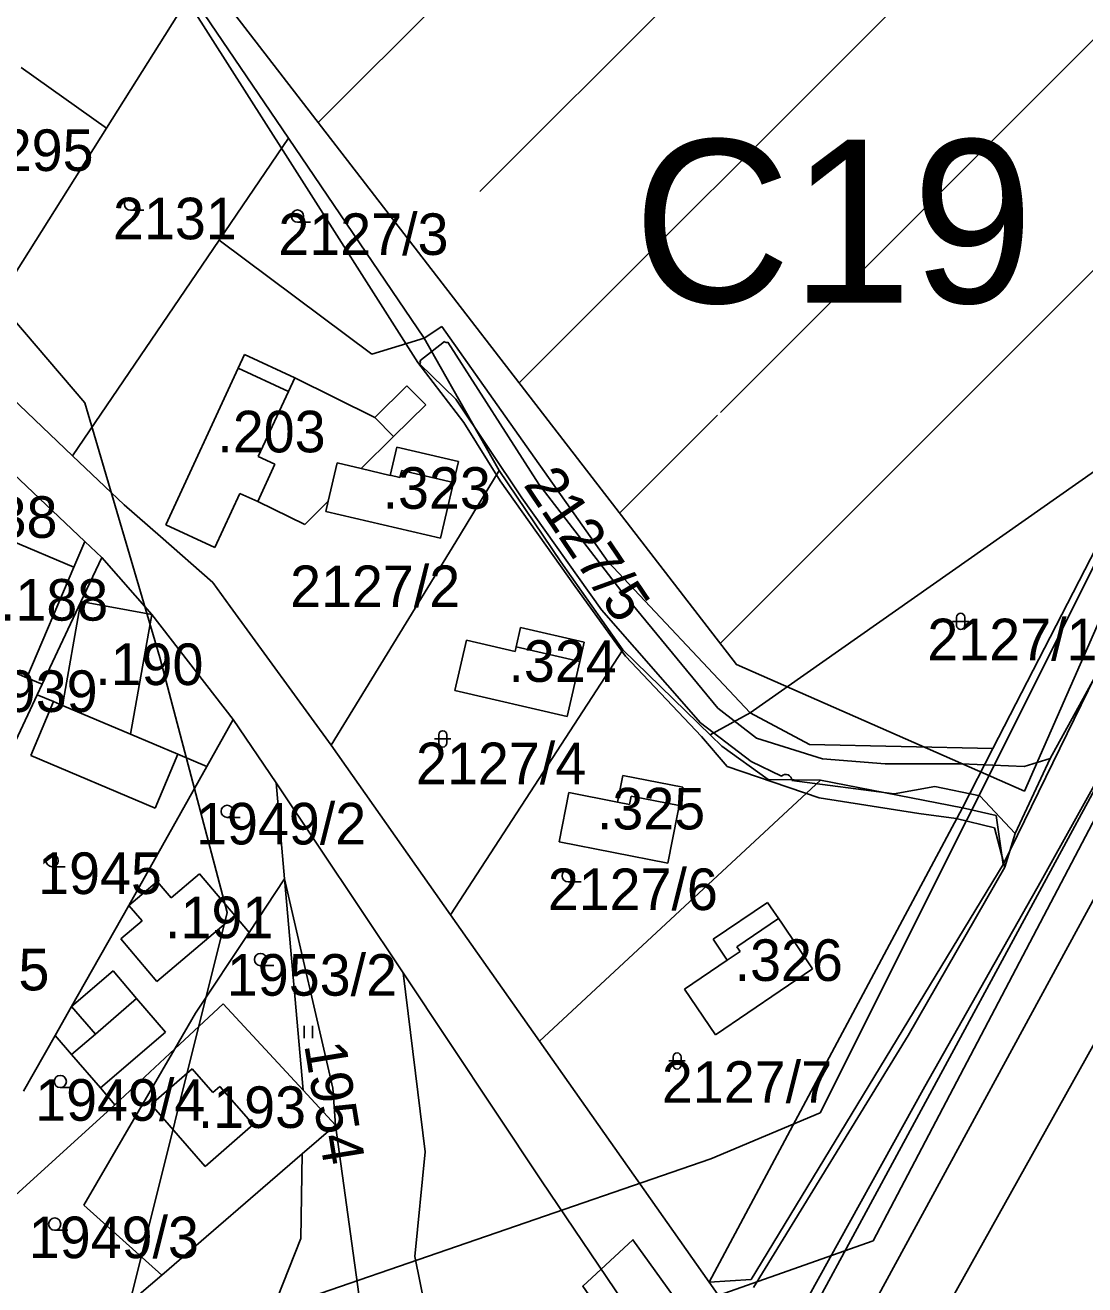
# Model space of a CAD drawing. Extents: x -564810 to -550519, y -1045831 to -1034011.
# Drawn here: x -553050.1 to -552920.1, y -1037817.5 to -1037663 of the extents above; entities that cross this region are included whole.
import ezdxf

# ---------------------------------------------------------------- set-up
doc = ezdxf.new("R2010")
doc.units = 0
for name, color, linetype in [('KN stav', 7, 'Continuous'), ('Lesní porost', 7, 'Continuous'), ('Obvod KPU', 7, 'Continuous'), ('označ pol cest', 7, 'Continuous'), ('Parcelní čísla', 7, 'Continuous'), ('Polní cesty stavající', 7, 'Continuous'), ('STG', 7, 'Continuous'), ('Vedení VN', 7, 'Continuous'), ('Vrstva 22', 7, 'Continuous'), ('Vrstva 39', 7, 'Continuous'), ('Vrstva 4', 7, 'Continuous'), ('Vrstva 5', 7, 'Continuous'), ('zamokř ploch', 7, 'Continuous')]:
    doc.layers.add(name, color=color, linetype=linetype)

msp = doc.modelspace()

# ---------------------------------------------------------------- linework, layer by layer
at = {"layer": 'KN stav'}
for p, q in [((-553029.74, -1037659.19), (-553040.1, -1037675.65)), ((-553017.77, -1037676.87), (-553029.74, -1037659.19)), ((-553040.1, -1037675.65), (-553050.55, -1037668.18)), ((-553040.1, -1037675.65), (-553057.47, -1037703.22)), ((-553017.77, -1037676.87), (-553026.28, -1037689.38)), ((-553001.14, -1037701.4), (-553017.77, -1037676.87)), ((-553026.28, -1037689.38), (-553044.24, -1037715.8)), ((-553007.55, -1037703.35), (-553026.28, -1037689.38)), ((-552998.99, -1037699.95), (-553001.14, -1037701.4)), ((-552978.62, -1037728.76), (-552998.99, -1037699.95)), ((-553001.14, -1037701.4), (-553004.2, -1037702.31)), ((-553001.14, -1037701.4), (-552999.17, -1037704.88)), ((-553004.2, -1037702.31), (-553007.55, -1037703.35)), ((-553057.47, -1037703.22), (-553044.24, -1037715.8)), ((-553023.94, -1037705.08), (-553023.16, -1037703.4)), ((-553023.16, -1037703.4), (-553017, -1037706.25)), ((-553032.82, -1037724.27), (-553023.94, -1037705.08)), ((-552999.17, -1037704.88), (-552991.93, -1037717.63)), ((-553017, -1037706.25), (-553007.21, -1037711.13)), ((-553007.21, -1037711.13), (-553003.26, -1037707.22)), ((-553003.26, -1037707.22), (-553002.45, -1037708.03)), ((-553002.45, -1037708.03), (-553000.95, -1037709.55)), ((-553000.95, -1037709.55), (-553004.9, -1037713.46)), ((-552911.07, -1037712.13), (-552961.16, -1037747.33)), ((-552931.42, -1037751.72), (-552911.07, -1037712.13)), ((-553004.9, -1037713.46), (-553008.86, -1037717.38)), ((-553005.31, -1037718.21), (-553004.5, -1037714.74)), ((-553004.5, -1037714.74), (-552996.95, -1037716.5)), ((-553044.24, -1037715.8), (-553037.91, -1037721.82)), ((-553011.81, -1037716.69), (-553012.91, -1037721.39)), ((-553008.86, -1037717.38), (-553011.81, -1037716.69)), ((-552996.95, -1037716.5), (-552997.55, -1037719.09)), ((-553042.73, -1037726.32), (-553051.49, -1037718.01)), ((-553008.86, -1037717.38), (-553005.31, -1037718.21)), ((-552997.27, -1037726.36), (-552991.93, -1037717.63)), ((-552991.93, -1037717.63), (-552997.27, -1037726.36)), ((-552991.93, -1037717.63), (-552984.37, -1037728.82)), ((-552984.37, -1037728.82), (-552991.93, -1037717.63)), ((-552997.55, -1037719.09), (-552999.15, -1037725.92)), ((-553023.73, -1037720.42), (-553026.8, -1037727.06)), ((-553021.55, -1037721.43), (-553023.73, -1037720.42)), ((-553015.77, -1037724.22), (-553021.55, -1037721.43)), ((-553012.91, -1037721.39), (-553015.77, -1037724.22)), ((-553013.2, -1037722.64), (-553012.91, -1037721.39)), ((-553037.91, -1037721.82), (-553033.48, -1037725.7)), ((-552999.15, -1037725.92), (-553013.2, -1037722.64)), ((-553026.8, -1037727.06), (-553032.82, -1037724.27)), ((-553040.67, -1037728.27), (-553042.73, -1037726.32)), ((-553033.48, -1037725.7), (-553027.04, -1037731.35)), ((-553012.54, -1037751.32), (-552997.27, -1037726.36)), ((-552997.27, -1037726.36), (-553012.54, -1037751.32)), ((-553043.22, -1037733.71), (-553040.67, -1037728.27)), ((-553034.53, -1037735.26), (-553040.67, -1037728.27)), ((-552984.37, -1037728.82), (-552976.8, -1037739.63)), ((-552976.8, -1037739.63), (-552984.37, -1037728.82)), ((-552961.16, -1037747.33), (-552978.62, -1037728.76)), ((-553027.04, -1037731.35), (-553024.91, -1037734.28)), ((-553047.97, -1037743.84), (-553043.22, -1037733.71)), ((-553024.56, -1037748.16), (-553034.53, -1037735.26)), ((-553024.91, -1037734.28), (-553012.54, -1037751.32)), ((-552900.02, -1037735.13), (-552954.01, -1037834.49)), ((-552989.32, -1037736.89), (-552989.86, -1037739.25)), ((-552989.86, -1037739.25), (-552989.32, -1037736.89)), ((-552981.52, -1037738.69), (-552989.32, -1037736.89)), ((-552989.32, -1037736.89), (-552981.52, -1037738.69)), ((-552995.96, -1037738.42), (-552997.39, -1037744.58)), ((-552997.39, -1037744.58), (-552995.96, -1037738.42)), ((-552989.99, -1037739.8), (-552995.96, -1037738.42)), ((-552995.96, -1037738.42), (-552989.99, -1037739.8)), ((-553057.58, -1037739.76), (-553049.84, -1037743.05)), ((-552976.8, -1037739.63), (-552997.91, -1037772.1)), ((-552997.91, -1037772.1), (-552976.8, -1037739.63)), ((-552989.86, -1037739.25), (-552989.99, -1037739.8)), ((-552989.99, -1037739.8), (-552989.86, -1037739.25)), ((-552982.06, -1037741.06), (-552981.52, -1037738.69)), ((-552981.52, -1037738.69), (-552982.06, -1037741.06)), ((-552976.8, -1037739.63), (-552966, -1037750.11)), ((-552966, -1037750.11), (-552976.8, -1037739.63)), ((-552983.62, -1037747.77), (-552982.06, -1037741.06)), ((-552982.06, -1037741.06), (-552983.62, -1037747.77)), ((-553049.84, -1037743.05), (-553047.97, -1037743.84)), ((-553048.57, -1037745.12), (-553047.97, -1037743.84)), ((-552997.39, -1037744.58), (-552983.62, -1037747.77)), ((-552983.62, -1037747.77), (-552997.39, -1037744.58)), ((-553056.54, -1037762.09), (-553048.57, -1037745.12)), ((-553046.59, -1037745.96), (-553049.38, -1037752.56)), ((-553048.57, -1037745.12), (-553046.59, -1037745.96)), ((-552953.88, -1037751.23), (-552961.16, -1037747.33)), ((-553024.56, -1037748.16), (-553027.79, -1037753.92)), ((-553019.29, -1037755.93), (-553024.56, -1037748.16)), ((-552966, -1037750.11), (-552964.63, -1037751.44)), ((-552964.63, -1037751.44), (-552966, -1037750.11)), ((-553049.38, -1037752.56), (-553034.12, -1037759.02)), ((-553034.12, -1037759.02), (-553031.33, -1037752.42)), ((-553031.33, -1037752.42), (-553027.79, -1037753.92)), ((-553012.54, -1037751.32), (-552997.91, -1037772.1)), ((-552997.91, -1037772.1), (-553012.54, -1037751.32)), ((-552964.63, -1037751.44), (-552958.98, -1037755.51)), ((-552958.98, -1037755.51), (-552964.63, -1037751.44)), ((-552931.42, -1037751.72), (-552953.88, -1037751.23)), ((-552935.15, -1037758.98), (-552931.42, -1037751.72)), ((-553027.79, -1037753.92), (-553037.34, -1037770.96)), ((-552952.54, -1037755.59), (-552987.02, -1037787.59)), ((-552987.02, -1037787.59), (-552952.54, -1037755.59)), ((-552976.78, -1037755.01), (-552977.43, -1037758.3)), ((-552977.43, -1037758.3), (-552976.78, -1037755.01)), ((-552969.44, -1037756.46), (-552976.78, -1037755.01)), ((-552976.78, -1037755.01), (-552969.44, -1037756.46)), ((-552958.98, -1037755.51), (-552952.54, -1037755.59)), ((-552952.54, -1037755.59), (-552958.98, -1037755.51)), ((-552952.54, -1037755.59), (-552935.15, -1037758.98)), ((-552935.15, -1037758.98), (-552952.54, -1037755.59)), ((-553003.73, -1037779.23), (-553019.29, -1037755.93)), ((-553019.29, -1037755.93), (-553018.25, -1037767.71)), ((-552983.4, -1037757.12), (-552984.6, -1037763.15)), ((-552984.6, -1037763.15), (-552983.4, -1037757.12)), ((-552977.43, -1037758.3), (-552983.4, -1037757.12)), ((-552983.4, -1037757.12), (-552977.43, -1037758.3)), ((-552969.88, -1037758.72), (-552969.44, -1037756.46)), ((-552969.44, -1037756.46), (-552969.88, -1037758.72)), ((-552970.09, -1037759.76), (-552969.88, -1037758.72)), ((-552969.88, -1037758.72), (-552970.09, -1037759.76)), ((-552971.28, -1037765.78), (-552970.09, -1037759.76)), ((-552970.09, -1037759.76), (-552971.28, -1037765.78)), ((-552935.15, -1037758.98), (-552931, -1037759.93)), ((-552931, -1037759.93), (-552935.15, -1037758.98)), ((-552931, -1037759.93), (-552930.17, -1037765.92)), ((-552930.17, -1037765.92), (-552931, -1037759.93)), ((-552984.6, -1037763.15), (-552971.28, -1037765.78)), ((-552971.28, -1037765.78), (-552984.6, -1037763.15)), ((-552930.17, -1037765.92), (-552961.04, -1037816.83)), ((-552961.04, -1037816.83), (-552930.17, -1037765.92)), ((-553037.34, -1037770.96), (-553033.88, -1037768.02)), ((-553033.88, -1037768.02), (-553032.18, -1037770.03)), ((-553032.18, -1037770.03), (-553028.69, -1037767.08)), ((-553028.69, -1037767.08), (-553024.35, -1037772.2)), ((-553018.25, -1037767.71), (-553022.6, -1037774.27)), ((-553012.33, -1037793.36), (-553018.25, -1037767.71)), ((-553015.97, -1037793.61), (-553018.25, -1037767.71)), ((-553037.34, -1037770.96), (-553044.36, -1037783.36)), ((-552959.05, -1037770.59), (-552965.72, -1037775.11)), ((-552965.72, -1037775.11), (-552959.05, -1037770.59)), ((-552957.31, -1037773.15), (-552959.05, -1037770.59)), ((-552959.05, -1037770.59), (-552957.31, -1037773.15)), ((-553024.35, -1037772.2), (-553022.6, -1037774.27)), ((-552997.91, -1037772.1), (-552987.02, -1037787.59)), ((-552987.02, -1037787.59), (-552997.91, -1037772.1)), ((-552953.52, -1037778.74), (-552957.31, -1037773.15)), ((-552957.31, -1037773.15), (-552953.52, -1037778.74)), ((-553022.6, -1037774.27), (-553029.17, -1037784.19)), ((-552965.72, -1037775.11), (-552963.98, -1037777.68)), ((-552963.98, -1037777.68), (-552965.72, -1037775.11)), ((-552963.98, -1037777.68), (-552969.23, -1037781.24)), ((-552969.23, -1037781.24), (-552963.98, -1037777.68)), ((-552965.44, -1037786.83), (-552953.52, -1037778.74)), ((-552953.52, -1037778.74), (-552965.44, -1037786.83)), ((-552986.77, -1037804.73), (-553003.73, -1037779.23)), ((-553003.73, -1037779.23), (-553001.02, -1037801.18)), ((-552969.23, -1037781.24), (-552965.44, -1037786.83)), ((-552965.44, -1037786.83), (-552969.23, -1037781.24)), ((-553044.36, -1037783.36), (-553046.38, -1037786.91)), ((-553031.7, -1037788.54), (-553025.77, -1037783.01)), ((-553025.77, -1037783.01), (-553015.97, -1037793.61)), ((-553029.17, -1037784.19), (-553031.7, -1037788.54)), ((-553050.27, -1037793.76), (-553046.38, -1037786.91)), ((-553046.38, -1037786.91), (-553044.37, -1037789.25)), ((-552987.02, -1037787.59), (-552966.19, -1037817.18)), ((-552966.19, -1037817.18), (-552987.02, -1037787.59)), ((-553044.37, -1037789.25), (-553040.84, -1037793.35)), ((-553031.7, -1037788.54), (-553042.85, -1037807.74)), ((-553039.07, -1037795.41), (-553031.7, -1037788.54)), ((-553040.84, -1037793.35), (-553039.07, -1037795.41)), ((-553015.97, -1037793.61), (-553012.02, -1037797.89)), ((-553012.02, -1037797.89), (-553012.33, -1037793.36)), ((-553039.07, -1037795.41), (-553058.2, -1037812.81)), ((-553012.02, -1037797.89), (-553016.1, -1037801.42)), ((-553012.02, -1037797.89), (-553008.07, -1037826.39)), ((-553033.3, -1037816.3), (-553016.1, -1037801.42)), ((-553016.1, -1037801.42), (-553016.27, -1037811.79)), ((-553001.02, -1037801.18), (-553002.27, -1037814.03)), ((-552971.26, -1037827.61), (-552986.77, -1037804.73)), ((-553042.85, -1037807.74), (-553033.3, -1037816.3)), ((-553016.27, -1037811.79), (-553022.22, -1037826.9)), ((-553002.27, -1037814.03), (-553001.03, -1037820.27)), ((-553033.3, -1037816.3), (-553037.74, -1037820.11)), ((-552961.04, -1037816.83), (-552966.19, -1037817.18)), ((-552966.19, -1037817.18), (-552961.04, -1037816.83)), ((-552966.19, -1037817.18), (-552954.01, -1037834.49))]:
    msp.add_line(p, q, dxfattribs=at)
at = {"layer": 'Lesní porost'}
for p, q in [((-553014.14, -1037674.95), (-552911.77, -1037572.58)), ((-552994.3, -1037683.39), (-552911.47, -1037600.57)), ((-552989.5, -1037706.88), (-552911.17, -1037628.55)), ((-552964.83, -1037710.49), (-552910.96, -1037656.63)), ((-552964.87, -1037738.82), (-552911.01, -1037684.96)), ((-552977.18, -1037722.85), (-552965.18, -1037710.85))]:
    msp.add_line(p, q, dxfattribs=at)
at = {"layer": 'Obvod KPU'}
for p, q in [((-553029.69, -1037660.7), (-553018.13, -1037678.87)), ((-553018.13, -1037678.87), (-553001.91, -1037704.35)), ((-553001.91, -1037704.35), (-552996.27, -1037711.74)), ((-552996.27, -1037711.74), (-552991.81, -1037718.9)), ((-552991.81, -1037718.9), (-552982.64, -1037731.83)), ((-552982.64, -1037731.83), (-552976.44, -1037740.39)), ((-552976.44, -1037740.39), (-552967.16, -1037750.24)), ((-552967.16, -1037750.24), (-552963.99, -1037753.94)), ((-552963.99, -1037753.94), (-552952.7, -1037757.75)), ((-552952.7, -1037757.75), (-552940.48, -1037759.68)), ((-552940.48, -1037759.68), (-552935.91, -1037760.31)), ((-552935.91, -1037760.31), (-552931.21, -1037761.44)), ((-552931.21, -1037761.44), (-552929.97, -1037766.27)), ((-552929.97, -1037766.27), (-552941.8, -1037786.93)), ((-552941.8, -1037786.93), (-552960.76, -1037817.81))]:
    msp.add_line(p, q, dxfattribs=at)
at = {"layer": 'Polní cesty stavající'}
for p, q in [((-552998.65, -1037701.81), (-553001.67, -1037704.17)), ((-552987.08, -1037719.28), (-552998.25, -1037701.88)), ((-553001.69, -1037704.56), (-552997.26, -1037708.86)), ((-552997.26, -1037708.86), (-552989.18, -1037720.98)), ((-552977.03, -1037732.33), (-552987.08, -1037719.28)), ((-552989.18, -1037720.98), (-552979.39, -1037734.72)), ((-552965.15, -1037746.75), (-552977.03, -1037732.33)), ((-552979.39, -1037734.72), (-552967.28, -1037748.56)), ((-552960.39, -1037750.44), (-552965.15, -1037746.75)), ((-552967.28, -1037748.56), (-552961.05, -1037753.29)), ((-552952.3, -1037753), (-552960.39, -1037750.44)), ((-552961.05, -1037753.29), (-552957.33, -1037755.12)), ((-552944.62, -1037753.6), (-552952.3, -1037753)), ((-552935.27, -1037753.61), (-552944.62, -1037753.6)), ((-552927.57, -1037753.94), (-552935.27, -1037753.61)), ((-552924.38, -1037752.93), (-552927.57, -1037753.94)), ((-552956.05, -1037755.62), (-552943.53, -1037757.29)), ((-552943.53, -1037757.29), (-552938.52, -1037756.37)), ((-552938.52, -1037756.37), (-552933.01, -1037757.52)), ((-552933.01, -1037757.52), (-552928.67, -1037762.15))]:
    msp.add_line(p, q, dxfattribs=at)
for points in [[(-552960.76, -1037817.81), (-552941.8, -1037786.93), (-552929.97, -1037766.27), (-552928.67, -1037762.15), (-552924.38, -1037752.93), (-552903.4, -1037714.73), (-552892.53, -1037691.5), (-552885, -1037675.77), (-552874.67, -1037648.23), (-552874.67, -1037648.23), (-552861.2, -1037606.24), (-552850.78, -1037573.23), (-552844.27, -1037541.11), (-552842.11, -1037542.55), (-552841.6, -1037538.6), (-552840.92, -1037529.94), (-552837.72, -1037513.24), (-552840.45, -1037515.35), (-552825.68, -1037468.2), (-552803.94, -1037397.99), (-552790.46, -1037357.53)], [(-552785.17, -1037359.05), (-552797.5, -1037398.18), (-552820.92, -1037471.8), (-552833.6, -1037513.63), (-552835.28, -1037521.77), (-552837.42, -1037534.38), (-552834.86, -1037539.46), (-552825.88, -1037544.97), (-552818.86, -1037554.44), (-552823.67, -1037553.78), (-552826.56, -1037549.47), (-552831.77, -1037545.13), (-552834.93, -1037543.55), (-552838.51, -1037542.9), (-552845.29, -1037574.84), (-552855.41, -1037608.33), (-552866.99, -1037642.38), (-552869.53, -1037649.96), (-552879.97, -1037677.73), (-552887.48, -1037694.58), (-552912.55, -1037744.63), (-552925.5, -1037767.94), (-552939.75, -1037793.18), (-552954.11, -1037819.1)], [(-552928.67, -1037762.15), (-552924.38, -1037752.93)]]:
    msp.add_lwpolyline(points, dxfattribs=at)
for centre, radius, start, end in [((-552998.41, -1037701.63), 0.3, 217.8523, 302.6975), ((-553001.91, -1037704.35), 0.3, 315.8756, 37.8523), ((-552956.8, -1037755.65), 0.75, 2.5466, 134.5767)]:
    msp.add_arc(centre, radius, start, end, dxfattribs=at)
at = {"layer": 'STG'}
msp.add_lwpolyline([(-553069.37, -1037817.75), (-553060.19, -1037787.43), (-553060.19, -1037767.22), (-553071.21, -1037738.73), (-553073.97, -1037702.9), (-553068.46, -1037687.28), (-553059.27, -1037690.04), (-553042.74, -1037709.33), (-553033.55, -1037740.57), (-553025.28, -1037771.81), (-553038.14, -1037823.26)], dxfattribs=at)
at = {"layer": 'Vedení VN'}
msp.add_line((-552946.11, -1037812.08), (-553022.11, -1037838.91), dxfattribs=at)
for points in [[(-554311.13, -1038894.55), (-554183.26, -1038768.06), (-553948.71, -1038736.97), (-553887.24, -1038715.77), (-553721.22, -1038534.86), (-553615.96, -1038471.97), (-553583.46, -1038409.78), (-553495.15, -1038284), (-553204.09, -1037884.03), (-552966, -1037802.05), (-552952.58, -1037796.4), (-552903.13, -1037697.47), (-552835.31, -1037471.34), (-552755.48, -1037231.07), (-552629.72, -1036976.67), (-552323.11, -1036754.78)], [(-552318.17, -1036790.68), (-552611.35, -1036998.44), (-552747, -1037286.75), (-552886.17, -1037729.13), (-552939.86, -1037825.23), (-553193.49, -1037916.39), (-553506.46, -1038353.11), (-553565.8, -1038423.21), (-553601.83, -1038493.17), (-553700.74, -1038549.7), (-553878.06, -1038746.16), (-554195.97, -1038818.23), (-554311.84, -1038929.18)], [(-552758.55, -1037278.62), (-552793.93, -1037392.61), (-552821.07, -1037475.75), (-552845.16, -1037552.06), (-552871.05, -1037634.86), (-552897.88, -1037720.24), (-552946.11, -1037812.08)]]:
    msp.add_lwpolyline(points, dxfattribs=at)
at = {"layer": 'Vrstva 39'}
msp.add_lwpolyline([(-552897.12, -1037940.43), (-552898.9, -1037938.1), (-552945.1, -1037870.48), (-552981.69, -1037817.65), (-552975.54, -1037811.96), (-552969.36, -1037820.6), (-552960.29, -1037833.27), (-552959.84, -1037829.57)], dxfattribs=at)
at = {"layer": 'Vrstva 4'}
for p, q in [((-553023.94, -1037705.08), (-553017.78, -1037707.93)), ((-553017.78, -1037707.93), (-553017, -1037706.25)), ((-553017.78, -1037707.93), (-553021.48, -1037715.91)), ((-553004.9, -1037713.46), (-553007.21, -1037711.12)), ((-553019.43, -1037716.86), (-553021.55, -1037721.43)), ((-553021.48, -1037715.91), (-553019.43, -1037716.86)), ((-553004.11, -1037718.49), (-553005.31, -1037718.2)), ((-553003.9, -1037717.61), (-553004.11, -1037718.49)), ((-552997.55, -1037719.09), (-553003.9, -1037717.61)), ((-553044.08, -1037729.49), (-553051.8, -1037726.21)), ((-553044.08, -1037729.49), (-553042.73, -1037726.31)), ((-553049.84, -1037743.05), (-553044.08, -1037729.49)), ((-553045.49, -1037746.42), (-553043.22, -1037733.7)), ((-553034.53, -1037735.26), (-553043.22, -1037733.7)), ((-553037.16, -1037749.95), (-553034.53, -1037735.26)), ((-552982.07, -1037741.06), (-552989.86, -1037739.25)), ((-552917.97, -1037741.01), (-552930.17, -1037765.92)), ((-553045.49, -1037746.42), (-553046.59, -1037745.96)), ((-553045.49, -1037746.42), (-553037.16, -1037749.95)), ((-552966.06, -1037750.05), (-552961.16, -1037747.33)), ((-553031.33, -1037752.42), (-553037.16, -1037749.95)), ((-552918.15, -1037755.25), (-552957.97, -1037828.87)), ((-552975.96, -1037758.59), (-552977.43, -1037758.3)), ((-552975.76, -1037757.56), (-552975.96, -1037758.59)), ((-552969.89, -1037758.72), (-552975.76, -1037757.56)), ((-552935.15, -1037758.98), (-552966.19, -1037817.18)), ((-553037.34, -1037770.95), (-553035.73, -1037772.86)), ((-553033.92, -1037780.3), (-553024.35, -1037772.2)), ((-552957.71, -1037772.56), (-552962.81, -1037776.02)), ((-553035.73, -1037772.86), (-553038.35, -1037775.07)), ((-553038.35, -1037775.07), (-553033.92, -1037780.3)), ((-552962.41, -1037776.61), (-552963.98, -1037777.67)), ((-552962.81, -1037776.02), (-552962.41, -1037776.61)), ((-553039.29, -1037779), (-553044.36, -1037783.36)), ((-553039.29, -1037779), (-553036.39, -1037782.38)), ((-553044.36, -1037783.36), (-553041.45, -1037786.74)), ((-553036.39, -1037782.38), (-553041.45, -1037786.74)), ((-553032.86, -1037786.49), (-553036.39, -1037782.38)), ((-553040.84, -1037793.35), (-553032.86, -1037786.49)), ((-553041.45, -1037786.74), (-553044.37, -1037789.24)), ((-553029.6, -1037791), (-553034.61, -1037795.38)), ((-553027.06, -1037793.92), (-553029.6, -1037791)), ((-553026.19, -1037793.15), (-553027.06, -1037793.92)), ((-553022.1, -1037797.83), (-553026.19, -1037793.15)), ((-553034.61, -1037795.38), (-553027.98, -1037802.97)), ((-553027.98, -1037802.97), (-553022.1, -1037797.83))]:
    msp.add_line(p, q, dxfattribs=at)
at = {"layer": 'Vrstva 5'}
msp.add_lwpolyline([(-552838.62, -1037227.28), (-552866, -1037405.86), (-552870.45, -1037458.52), (-552836.04, -1037517.97), (-552862.96, -1037609.95), (-552927.56, -1037756.93), (-552962.86, -1037741.42), (-553024.92, -1037660.97), (-553063.49, -1037606.64), (-553079.67, -1037615.16), (-553096.76, -1037617.23), (-553113.85, -1037619.29), (-553224.66, -1037468.33), (-553256.7, -1037419.19), (-553309.59, -1037318.2)], dxfattribs=at)
at = {"layer": 'zamokř ploch'}
for p, q in [((-553037.13, -1037685.69), (-553035.53, -1037685.69)), ((-553016.67, -1037687.16), (-553015.07, -1037687.16)), ((-552936.37, -1037736.12), (-552934.37, -1037736.12)), ((-552935.87, -1037735.62), (-552935.87, -1037736.62)), ((-552934.87, -1037735.62), (-552934.87, -1037736.62)), ((-552999.86, -1037750.53), (-552997.86, -1037750.53)), ((-552999.36, -1037750.03), (-552999.36, -1037751.03)), ((-552998.36, -1037750.03), (-552998.36, -1037751.03)), ((-553025.29, -1037760.17), (-553023.69, -1037760.17)), ((-553046.75, -1037766.22), (-553045.15, -1037766.22)), ((-552983.48, -1037768.08), (-552981.89, -1037768.08)), ((-553021.2, -1037778.34), (-553019.59, -1037778.34)), ((-553015.84, -1037785.74), (-553015.84, -1037787.24)), ((-553014.84, -1037785.74), (-553014.84, -1037787.24)), ((-552970.63, -1037789.54), (-552970.63, -1037790.54)), ((-552969.63, -1037789.54), (-552969.63, -1037790.54)), ((-552971.13, -1037790.04), (-552969.13, -1037790.04)), ((-553045.75, -1037793.3), (-553044.15, -1037793.3)), ((-553046.44, -1037810.79), (-553044.84, -1037810.79))]:
    msp.add_line(p, q, dxfattribs=at)
for centre in [(-553037.13, -1037684.94), (-553016.67, -1037686.41), (-553025.29, -1037759.42), (-553046.75, -1037765.47), (-552983.48, -1037767.33), (-553021.2, -1037777.6), (-553045.75, -1037792.55), (-553046.44, -1037810.04)]:
    msp.add_circle(centre, 0.75, dxfattribs=at)
for centre, start, end in [((-552935.37, -1037735.62), 0, 180), ((-552935.37, -1037736.62), 180, 0), ((-552998.86, -1037750.03), 0, 180), ((-552998.86, -1037751.03), 180, 0), ((-552970.13, -1037789.54), 0, 180), ((-552970.13, -1037790.54), 180, 0)]:
    msp.add_arc(centre, 0.5, start, end, dxfattribs=at)

# ---------------------------------------------------------------- texts
at = {"layer": 'označ pol cest'}
msp.add_text('C19', height=20, dxfattribs=at).set_placement((-552975.51, -1037697.05))
at = {"layer": 'Parcelní čísla'}
for s, p in [('2131', (-553039.29, -1037689.26)), ('2127/3', (-553019.02, -1037691.18)), ('1938', (-553061.27, -1037725.88)), ('2127/2', (-553017.58, -1037734.37)), ('2127/1', (-552939.45, -1037740.89)), ('1939', (-553056.35, -1037747.23)), ('2127/4', (-553002.14, -1037756.09)), ('1949/2', (-553029.11, -1037763.48)), ('1945', (-553048.47, -1037769.56)), ('2127/6', (-552985.99, -1037771.53)), ('1945', (-553062.26, -1037781.38)), ('1953/2', (-553025.33, -1037782.03)), ('2127/7', (-552972, -1037795.17)), ('1949/4', (-553048.83, -1037797.37)), ('1949/3', (-553049.62, -1037814.22))]:
    msp.add_text(s, height=5.1, dxfattribs=at).set_placement(p)
for s, rotation, p in [('2127/5', 304.0552, (-552989.06, -1037719.36)), ('1954', 279.3079, (-553015.86, -1037788.06))]:
    msp.add_text(s, height=5.1, rotation=rotation, dxfattribs=at).set_placement(p)
at = {"layer": 'Vrstva 22'}
for s, p in [('.295', (-553054.95, -1037680.88)), ('.203', (-553026.5, -1037715.39)), ('.323', (-553006.24, -1037722.31)), ('.188', (-553053.15, -1037736.03)), ('.324', (-552990.81, -1037743.54)), ('.190', (-553041.48, -1037743.93)), ('.325', (-552979.96, -1037761.64)), ('.191', (-553032.91, -1037774.98)), ('.326', (-552963.08, -1037780.22)), ('.193', (-553028.9, -1037798.25))]:
    msp.add_text(s, height=5.1, dxfattribs=at).set_placement(p)

doc.saveas('drawing.dxf')
